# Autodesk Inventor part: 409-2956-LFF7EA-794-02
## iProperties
Created: 2010-11
Part Number: 409-2956-LFF7EA-794-02
Cost Center: 0 lbmass
Material: A304 STAINLESS STEEL
Document SubType Name: Sheet Metal
Designer: S. Boerckel
Authority: 0 in^3
Mass: 794.445 g
Surface Area: 357.51 cm^2
Volume: 98.3224 cm^3
Density: 8.08 g/cm^3
Flat Pattern Width: 5.08 cm
Flat Pattern Length: 35.56 cm
Flat Pattern Area: 180.645 cm^2
Sheet Metal Rule: 1/4"Thk
Description: 2" PIPE ANGLE SUPPORT
SaveDate: 2008-01-15
SaveTime: 10:24
FileName: Sheet Metal
Wide: =<Flat Pattern Width>cm
Length: =<Flat Pattern Length>cm
Thickness: 0.2500 in
SMR: =<Sheet Metal Rule> - <Material>
Author: S. Boerckel
Revision Number: 0
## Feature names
1. Plate1
